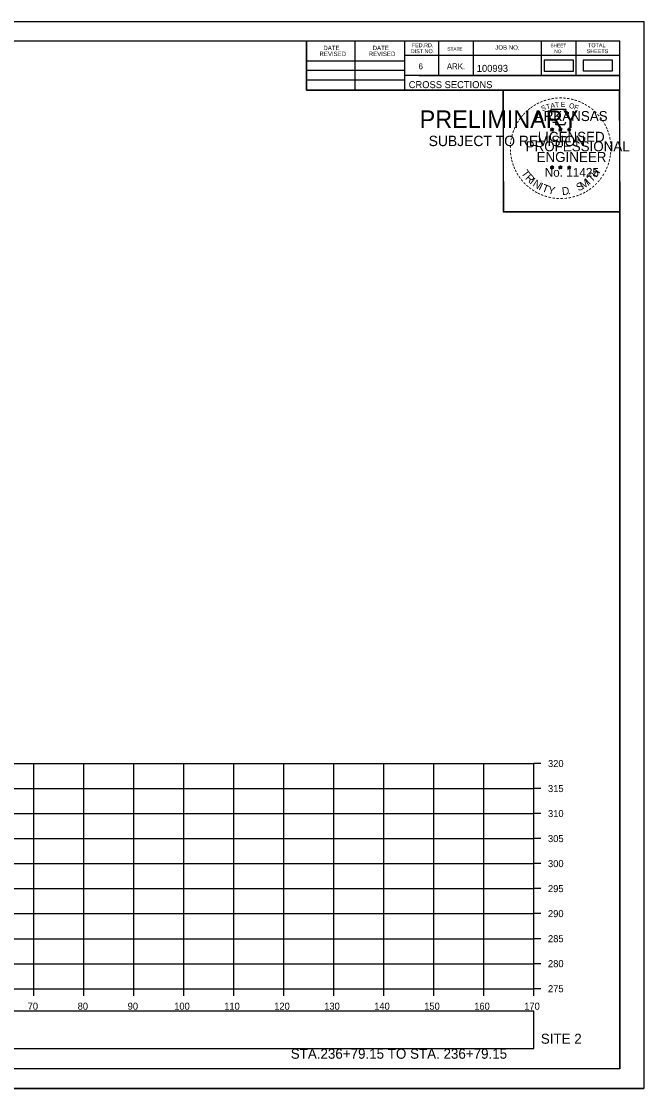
# Model space of a CAD drawing. Extents: x 4667 to 1632277, y -2100 to 724501.
# Drawn here: x 5844.7 to 5969.1, y 1663 to 1876.3 of the extents above; entities that cross this region are included whole.
import ezdxf

# ---------------------------------------------------------------- set-up
doc = ezdxf.new("R2010")
doc.units = 0
for name, color, linetype in [('Default', 7, 'Continuous'), ('R_Axis', 7, 'Continuous'), ('R_Axis Annot', 7, 'Continuous'), ('R_Border', 7, 'Continuous'), ('R_Border PE', 7, 'Continuous'), ('R_Border Prem', 7, 'Continuous'), ('R_Draft', 7, 'Continuous'), ('R_Grid', 7, 'Continuous'), ('R_No Plot', 7, 'Continuous'), ('R_Proposed CofA', 7, 'Continuous')]:
    doc.layers.add(name, color=color, linetype=linetype)

msp = doc.modelspace()

# ---------------------------------------------------------------- linework, layer by layer
at = {"layer": 'Default'}
for points in [[(5949.24, 1866.34), (5955.07, 1866.34), (5955.07, 1868.53), (5949.24, 1868.53)], [(5957.04, 1866.4), (5962.87, 1866.4), (5962.87, 1868.58), (5957.04, 1868.58)]]:
    msp.add_lwpolyline(points, close=True, dxfattribs=at)
at = {"layer": 'R_Axis'}
for p, q in [((5947.18, 1682.96), (5947.18, 1727.96)), ((5948.58, 1727.96), (5947.18, 1727.96)), ((5948.58, 1722.96), (5947.18, 1722.96)), ((5948.58, 1717.96), (5947.18, 1717.96)), ((5948.58, 1712.96), (5947.18, 1712.96)), ((5948.58, 1707.96), (5947.18, 1707.96)), ((5948.58, 1702.96), (5947.18, 1702.96)), ((5948.58, 1697.96), (5947.18, 1697.96)), ((5948.58, 1692.96), (5947.18, 1692.96)), ((5948.58, 1687.96), (5947.18, 1687.96)), ((5667.18, 1682.96), (5947.18, 1682.96)), ((5847.18, 1681.56), (5847.18, 1682.96)), ((5857.18, 1681.56), (5857.18, 1682.96)), ((5867.18, 1681.56), (5867.18, 1682.96)), ((5877.18, 1681.56), (5877.18, 1682.96)), ((5887.18, 1681.56), (5887.18, 1682.96)), ((5897.18, 1681.56), (5897.18, 1682.96)), ((5907.18, 1681.56), (5907.18, 1682.96)), ((5917.18, 1681.56), (5917.18, 1682.96)), ((5927.18, 1681.56), (5927.18, 1682.96)), ((5937.18, 1681.56), (5937.18, 1682.96)), ((5947.18, 1681.56), (5947.18, 1682.96)), ((5948.58, 1682.96), (5947.18, 1682.96))]:
    msp.add_line(p, q, dxfattribs=at)
at = {"layer": 'R_Border'}
for p, q in [((5648.18, 1872.42), (5964.36, 1872.42)), ((5901.72, 1862.54), (5901.72, 1872.42)), ((5911.4, 1862.54), (5911.4, 1872.42)), ((5921.26, 1872.42), (5921.26, 1862.54)), ((5928.1, 1872.42), (5928.1, 1865.48)), ((5935.04, 1872.42), (5935.04, 1865.48)), ((5948.62, 1872.42), (5948.62, 1865.48)), ((5955.56, 1872.42), (5955.56, 1865.48)), ((5964.36, 1666.96), (5964.36, 1872.42)), ((5964.36, 1869.48), (5921.26, 1869.48)), ((5964.36, 1869.5), (5964.36, 1869.5)), ((5901.72, 1868.4), (5921.26, 1868.4)), ((5901.72, 1866.54), (5921.26, 1866.54)), ((5901.72, 1864.6), (5921.26, 1864.6)), ((5964.36, 1865.48), (5921.26, 1865.48)), ((5924.22, 1865.48), (5964.36, 1865.48)), ((5964.36, 1862.54), (5901.72, 1862.54)), ((5964.36, 1666.96), (5648.18, 1666.96))]:
    msp.add_line(p, q, dxfattribs=at)
at = {"layer": 'R_Border PE'}
for p, q in [((5950.45, 1854.8), (5950.8, 1854.69)), ((5950.45, 1854.8), (5950.7, 1854.75)), ((5950.45, 1854.8), (5950.69, 1854.68)), ((5950.58, 1854.39), (5950.8, 1854.69)), ((5950.58, 1854.39), (5950.71, 1854.63)), ((5950.58, 1854.39), (5950.8, 1854.61)), ((5950.8, 1855.05), (5950.76, 1854.8)), ((5950.8, 1854.69), (5950.8, 1855.05)), ((5950.8, 1855.05), (5950.85, 1854.8)), ((5951.15, 1854.8), (5950.8, 1854.69)), ((5951.01, 1854.39), (5950.8, 1854.69)), ((5951.01, 1854.39), (5950.8, 1854.6)), ((5951.15, 1854.8), (5950.86, 1854.75)), ((5951.01, 1854.39), (5950.87, 1854.68)), ((5951.15, 1854.8), (5950.94, 1854.7)), ((5952.12, 1854.8), (5952.47, 1854.69)), ((5952.12, 1854.8), (5952.37, 1854.75)), ((5952.12, 1854.8), (5952.36, 1854.68)), ((5952.25, 1854.39), (5952.47, 1854.69)), ((5952.25, 1854.39), (5952.38, 1854.63)), ((5952.25, 1854.39), (5952.47, 1854.61)), ((5952.47, 1855.05), (5952.43, 1854.8)), ((5952.47, 1854.69), (5952.47, 1855.05)), ((5952.47, 1855.05), (5952.52, 1854.8)), ((5952.82, 1854.8), (5952.47, 1854.69)), ((5952.68, 1854.39), (5952.47, 1854.69)), ((5952.68, 1854.39), (5952.47, 1854.6)), ((5952.82, 1854.8), (5952.53, 1854.75)), ((5952.68, 1854.39), (5952.54, 1854.68)), ((5952.82, 1854.8), (5952.61, 1854.7)), ((5953.88, 1854.79), (5954.23, 1854.68)), ((5953.88, 1854.79), (5954.14, 1854.74)), ((5953.88, 1854.79), (5954.12, 1854.66)), ((5954.02, 1854.38), (5954.23, 1854.68)), ((5954.02, 1854.38), (5954.14, 1854.62)), ((5954.02, 1854.38), (5954.23, 1854.6)), ((5954.23, 1855.04), (5954.19, 1854.79)), ((5954.23, 1854.68), (5954.23, 1855.04)), ((5954.23, 1855.04), (5954.28, 1854.79)), ((5954.58, 1854.79), (5954.23, 1854.68)), ((5954.45, 1854.38), (5954.23, 1854.68)), ((5954.45, 1854.38), (5954.23, 1854.59)), ((5954.58, 1854.79), (5954.29, 1854.74)), ((5954.45, 1854.38), (5954.31, 1854.67)), ((5954.58, 1854.79), (5954.38, 1854.68)), ((5950.45, 1847.23), (5950.79, 1847.11)), ((5950.45, 1847.23), (5950.7, 1847.18)), ((5950.45, 1847.23), (5950.68, 1847.1)), ((5950.58, 1846.82), (5950.79, 1847.11)), ((5950.58, 1846.82), (5950.7, 1847.06)), ((5950.58, 1846.82), (5950.79, 1847.03)), ((5950.79, 1847.48), (5950.75, 1847.23)), ((5950.79, 1847.11), (5950.79, 1847.48)), ((5950.79, 1847.48), (5950.84, 1847.23)), ((5951.14, 1847.23), (5950.79, 1847.11)), ((5951.01, 1846.82), (5950.79, 1847.11)), ((5951.01, 1846.82), (5950.79, 1847.03)), ((5951.14, 1847.23), (5950.86, 1847.18)), ((5951.01, 1846.82), (5950.87, 1847.11)), ((5951.14, 1847.23), (5950.94, 1847.12)), ((5952.11, 1847.23), (5952.46, 1847.11)), ((5952.11, 1847.23), (5952.37, 1847.18)), ((5952.11, 1847.23), (5952.35, 1847.1)), ((5952.25, 1846.82), (5952.46, 1847.11)), ((5952.25, 1846.82), (5952.37, 1847.06)), ((5952.25, 1846.82), (5952.46, 1847.03)), ((5952.46, 1847.48), (5952.42, 1847.23)), ((5952.46, 1847.11), (5952.46, 1847.48)), ((5952.46, 1847.48), (5952.51, 1847.23)), ((5952.81, 1847.23), (5952.46, 1847.11)), ((5952.68, 1846.82), (5952.46, 1847.11)), ((5952.68, 1846.82), (5952.46, 1847.03)), ((5952.81, 1847.23), (5952.52, 1847.18)), ((5952.68, 1846.82), (5952.54, 1847.11)), ((5952.81, 1847.23), (5952.61, 1847.12)), ((5953.88, 1847.22), (5954.23, 1847.1)), ((5953.88, 1847.22), (5954.13, 1847.17)), ((5953.88, 1847.22), (5954.12, 1847.09)), ((5954.01, 1846.81), (5954.23, 1847.1)), ((5954.01, 1846.81), (5954.14, 1847.05)), ((5954.01, 1846.81), (5954.23, 1847.02)), ((5954.23, 1847.47), (5954.19, 1847.22)), ((5954.23, 1847.1), (5954.23, 1847.47)), ((5954.23, 1847.47), (5954.28, 1847.22)), ((5954.58, 1847.22), (5954.23, 1847.1)), ((5954.44, 1846.81), (5954.23, 1847.1)), ((5954.44, 1846.81), (5954.23, 1847.02)), ((5954.58, 1847.22), (5954.29, 1847.17)), ((5954.44, 1846.81), (5954.31, 1847.1)), ((5954.58, 1847.22), (5954.37, 1847.11))]:
    msp.add_line(p, q, dxfattribs=at)
for points in [[(5950.49, 1858.68), (5950.76, 1857.85)], [(5954, 1857.75), (5954.14, 1858.04), (5953.46, 1858.01), (5953.61, 1858.68), (5950.49, 1858.68)], [(5950.98, 1856.25), (5950.98, 1856.17), (5951.55, 1856.15), (5951.49, 1855.67), (5953.36, 1855.67), (5953.56, 1856.21)], [(5950.8, 1855.05), (5951.01, 1854.39), (5950.45, 1854.8), (5951.15, 1854.8), (5950.58, 1854.39), (5950.8, 1855.05)], [(5952.47, 1855.05), (5952.68, 1854.39), (5952.12, 1854.8), (5952.82, 1854.8), (5952.25, 1854.39), (5952.47, 1855.05)], [(5954.23, 1855.04), (5954.45, 1854.38), (5953.88, 1854.79), (5954.58, 1854.79), (5954.02, 1854.38), (5954.23, 1855.04)], [(5950.79, 1847.48), (5951.01, 1846.82), (5950.45, 1847.23), (5951.14, 1847.23), (5950.58, 1846.82), (5950.79, 1847.48)], [(5952.46, 1847.48), (5952.68, 1846.82), (5952.11, 1847.23), (5952.81, 1847.23), (5952.25, 1846.82), (5952.46, 1847.48)], [(5954.23, 1847.47), (5954.44, 1846.81), (5953.88, 1847.22), (5954.58, 1847.22), (5954.01, 1846.81), (5954.23, 1847.47)]]:
    msp.add_lwpolyline(points, dxfattribs=at)
for centre, radius in [((5950.8, 1854.69), 0.172), ((5950.8, 1854.69), 0.145), ((5950.8, 1854.69), 0.116), ((5950.8, 1854.69), 0.0991), ((5950.8, 1854.69), 0.0747), ((5950.8, 1854.69), 0.0495), ((5950.8, 1854.69), 0.0296), ((5952.47, 1854.69), 0.172), ((5952.47, 1854.69), 0.145), ((5952.47, 1854.69), 0.116), ((5952.47, 1854.69), 0.0991), ((5952.47, 1854.69), 0.0747), ((5952.47, 1854.69), 0.0495), ((5952.47, 1854.69), 0.0296), ((5954.23, 1854.67), 0.172), ((5954.23, 1854.67), 0.145), ((5954.23, 1854.67), 0.116), ((5954.23, 1854.67), 0.0991), ((5954.23, 1854.67), 0.0747), ((5954.23, 1854.67), 0.0495), ((5954.23, 1854.67), 0.0296), ((5950.79, 1847.11), 0.172), ((5950.79, 1847.11), 0.145), ((5950.79, 1847.11), 0.116), ((5950.79, 1847.11), 0.0991), ((5950.79, 1847.11), 0.0747), ((5950.79, 1847.11), 0.0495), ((5950.79, 1847.11), 0.0296), ((5952.46, 1847.11), 0.172), ((5952.46, 1847.11), 0.145), ((5952.46, 1847.11), 0.116), ((5952.46, 1847.11), 0.0991), ((5952.46, 1847.11), 0.0747), ((5952.46, 1847.11), 0.0495), ((5952.46, 1847.11), 0.0296), ((5954.23, 1847.1), 0.172), ((5954.23, 1847.1), 0.145), ((5954.23, 1847.1), 0.116), ((5954.23, 1847.1), 0.0991), ((5954.23, 1847.1), 0.0747), ((5954.23, 1847.1), 0.0495), ((5954.23, 1847.1), 0.0296)]:
    msp.add_circle(centre, radius, dxfattribs=at)
at = {"layer": 'R_Grid'}
for p, q in [((5667.18, 1727.96), (5947.18, 1727.96)), ((5847.18, 1682.96), (5847.18, 1727.96)), ((5857.18, 1682.96), (5857.18, 1727.96)), ((5867.18, 1682.96), (5867.18, 1727.96)), ((5877.18, 1682.96), (5877.18, 1727.96)), ((5887.18, 1682.96), (5887.18, 1727.96)), ((5897.18, 1682.96), (5897.18, 1727.96)), ((5907.18, 1682.96), (5907.18, 1727.96)), ((5917.18, 1682.96), (5917.18, 1727.96)), ((5927.18, 1682.96), (5927.18, 1727.96)), ((5937.18, 1682.96), (5937.18, 1727.96)), ((5947.18, 1682.96), (5947.18, 1727.96)), ((5667.18, 1722.96), (5947.18, 1722.96)), ((5667.18, 1717.96), (5947.18, 1717.96)), ((5667.18, 1712.96), (5947.18, 1712.96)), ((5667.18, 1707.96), (5947.18, 1707.96)), ((5667.18, 1702.96), (5947.18, 1702.96)), ((5667.18, 1697.96), (5947.18, 1697.96)), ((5667.18, 1692.96), (5947.18, 1692.96)), ((5667.18, 1687.96), (5947.18, 1687.96)), ((5667.18, 1682.96), (5947.18, 1682.96))]:
    msp.add_line(p, q, dxfattribs=at)
at = {"layer": 'R_No Plot'}
for p, q in [((5635.78, 1876.32), (5969.12, 1876.32)), ((5940.4, 1840.09), (5940.4, 1840.09)), ((5635.78, 1662.98), (5969.12, 1662.98))]:
    msp.add_line(p, q, dxfattribs=at)
for points in [[(5635.78, 1876.32), (5969.12, 1876.32), (5969.12, 1662.98), (5635.78, 1662.98)], [(5882.1, 1872.42), (5901.72, 1872.42), (5901.72, 1862.54), (5917.84, 1862.54), (5941.04, 1862.54), (5941.04, 1838.21), (5964.36, 1838.21), (5964.36, 1666.96), (5648.18, 1666.96), (5648.18, 1872.42)], [(5941.04, 1862.54), (5964.24, 1862.54), (5964.36, 1838.21), (5941.16, 1838.21)]]:
    msp.add_lwpolyline(points, close=True, dxfattribs=at)
at = {"layer": 'R_Proposed CofA'}
msp.add_lwpolyline([(5667.23, 1671.02), (5947.13, 1671.02), (5947.13, 1678.44), (5667.23, 1678.44)], close=True, dxfattribs=at)

# ---------------------------------------------------------------- texts
at = {"layer": 'R_Axis Annot'}
for s, p in [('320', (5949.98, 1727.26)), ('315', (5949.98, 1722.26)), ('310', (5949.98, 1717.26)), ('305', (5949.98, 1712.26)), ('300', (5949.98, 1707.26)), ('295', (5949.98, 1702.26)), ('290', (5949.98, 1697.26)), ('285', (5949.98, 1692.26)), ('280', (5949.98, 1687.26)), ('275', (5949.98, 1682.26)), ('70', (5845.92, 1678.76)), ('80', (5855.92, 1678.76)), ('90', (5865.92, 1678.76)), ('100', (5875.22, 1678.76)), ('110', (5885.22, 1678.76)), ('120', (5895.22, 1678.76)), ('130', (5905.22, 1678.76)), ('140', (5915.22, 1678.76)), ('150', (5925.22, 1678.76)), ('160', (5935.22, 1678.76)), ('170', (5945.22, 1678.76))]:
    msp.add_text(s, height=1.4, dxfattribs=at).set_placement(p)
at = {"layer": 'R_Border'}
for s, height, p in [('DATE', 0.879, (5905.06, 1870.56)), ('DATE', 0.879, (5914.92, 1870.56)), ('FED.RD.', 0.782, (5922.74, 1871.14)), ('STATE', 0.684, (5929.86, 1870.46)), ('JOB NO.', 0.879, (5939.44, 1870.66)), ('SHEET', 0.684, (5950.48, 1871.14)), ('TOTAL', 0.782, (5958, 1871.14)), ('REVISED', 0.879, (5904.28, 1869.38)), ('REVISED', 0.879, (5914.14, 1869.38)), ('DIST.NO.', 0.782, (5922.54, 1869.96)), ('NO.', 0.684, (5951.26, 1869.96)), ('SHEETS', 0.782, (5957.72, 1869.96)), ('6', 1.17, (5924.1, 1866.74)), ('ARK.', 1.172, (5929.76, 1866.74)), ('100993', 1.4, (5935.74, 1866.22)), ('CROSS SECTIONS', 1.4, (5922.13, 1862.97))]:
    msp.add_text(s, height=height, rotation=360, dxfattribs=at).set_placement(p)
at = {"layer": 'R_Border PE'}
for s, height, rotation, p in [('-', 1.6, 24.3072, (5948.6, 1859.53)), ('-', 1.6, 19.1761, (5949.24, 1859.8)), ('-', 1.6, 13.6301, (5949.99, 1860.04)), ('-', 1.6, 10.2193, (5950.67, 1860.21)), ('-', 1.6, 5.8968, (5951.39, 1860.32)), ('-', 1.6, 0.1862, (5952.17, 1860.39)), ('-', 1.6, 357.743, (5952.89, 1860.38)), ('-', 1.6, 352.1617, (5953.63, 1860.32)), ('-', 1.6, 347.2049, (5954.35, 1860.21)), ('-', 1.6, 342.3362, (5954.99, 1860.05)), ('-', 1.6, 337.8551, (5955.72, 1859.83)), ('-', 1.6, 42.9622, (5945.89, 1857.66)), ('-', 1.6, 38.9507, (5946.32, 1858.07)), ('-', 1.6, 36.2317, (5946.8, 1858.45)), ('-', 1.6, 34.0636, (5947.37, 1858.85)), ('ARKANSAS', 2, 360, (5947.34, 1856.39)), ('-', 1.6, 28.7918, (5947.97, 1859.22)), ('S', 1, 21.594, (5948.84, 1858.35)), ('T', 1, 16.4036, (5949.76, 1858.69)), ('A', 1, 11.2132, (5950.58, 1858.94)), ('T', 1, 6.0228, (5951.43, 1859.1)), ('E', 1, 0.8323, (5952.54, 1859.21)), ('O', 1, 350.4515, (5954.14, 1859)), ('F', 1, 340.0707, (5955.1, 1858.77)), ('-', 1.6, 334.1211, (5956.35, 1859.56)), ('-', 1.6, 329.6409, (5956.93, 1859.27)), ('-', 1.6, 325.8627, (5957.58, 1858.91)), ('-', 1.6, 320.5297, (5958.19, 1858.49)), ('-', 1.6, 315.5786, (5958.78, 1858)), ('-', 1.6, 58.0706, (5944.3, 1855.6)), ('-', 1.6, 54.2325, (5944.62, 1856.13)), ('-', 1.6, 50.6142, (5945.04, 1856.69)), ('-', 1.6, 48.423, (5945.44, 1857.18)), ('-', 1.6, 309.8797, (5959.35, 1857.45)), ('-', 1.6, 306.6522, (5959.88, 1856.85)), ('-', 1.4, 303.6753, (5960.36, 1856.28)), ('-', 1.6, 72.3945, (5943.51, 1853.74)), ('-', 1.6, 67.7743, (5943.73, 1854.37)), ('-', 1.6, 62.8713, (5943.98, 1854.99)), ('LICENSED', 2, 360, (5947.94, 1852.24)), ('DWB', 0.01, 360, (5950.79, 1854.68)), ('DWB', 0.01, 360, (5952.46, 1854.68)), ('DWB', 0.01, 360, (5954.22, 1854.67)), ('-', 1.6, 299.6684, (5960.68, 1855.67)), ('-', 1.6, 294.6628, (5961.01, 1855.06)), ('-', 1.6, 290.5728, (5961.26, 1854.48)), ('-', 1.6, 285.1233, (5961.5, 1853.9)), ('-', 1.6, 85.1863, (5943.1, 1851.63)), ('-', 1.6, 81.2013, (5943.18, 1852.32)), ('-', 1.6, 75.461, (5943.31, 1853.03)), ('PROFESSIONAL', 2, 360, (5945.52, 1850.34)), ('-', 1.6, 280.5493, (5961.7, 1853.16)), ('-', 1.6, 276.5962, (5961.86, 1852.39)), ('-', 1.6, 94.1959, (5943.11, 1850.2)), ('-', 1.6, 89.0622, (5943.08, 1850.93)), ('-', 1.6, 98.9479, (5943.18, 1849.53)), ('ENGINEER', 2, 360, (5947.7, 1848.21)), ('-', 1.6, 263.5172, (5961.94, 1850.37)), ('-', 1.6, 274.3301, (5961.92, 1851.67)), ('-', 1.6, 269.9407, (5961.95, 1851.04)), ('-', 1.6, 101.7149, (5943.32, 1848.8)), ('-', 1.6, 105.4578, (5943.48, 1848.21)), ('-', 1.6, 109.0874, (5943.7, 1847.57)), ('-', 1.6, 252.8681, (5961.57, 1848.32)), ('-', 1.6, 255.7626, (5961.75, 1849.04)), ('-', 1.6, 260.9953, (5961.86, 1849.72)), ('-', 1.6, 114.0643, (5943.95, 1846.98)), ('-', 1.6, 115.7289, (5944.25, 1846.36)), ('-', 1.6, 120.4471, (5944.61, 1845.77)), ('-', 1.6, 125.8934, (5945.01, 1845.21)), ('T', 1.54, 306.0406, (5944.55, 1845.95)), ('R', 1.54, 314.005, (5945.32, 1844.91)), ('No. 11425', 1.757, 360, (5949.33, 1845.26)), ('DWB', 0.01, 360, (5950.78, 1847.11)), ('DWB', 0.01, 360, (5952.45, 1847.11)), ('DWB', 0.01, 360, (5954.22, 1847.1)), ('T', 1.54, 46.6444, (5958.78, 1844.05)), ('H', 1.54, 54.6088, (5959.67, 1844.99)), ('-', 1.6, 239.0712, (5960.69, 1846.27)), ('-', 1.6, 244.6197, (5961.09, 1847.02)), ('-', 1.6, 247.8887, (5961.35, 1847.65)), ('-', 1.6, 130.7181, (5945.48, 1844.66)), ('-', 1.6, 134.2238, (5945.99, 1844.12)), ('-', 1.6, 138.9338, (5946.52, 1843.65)), ('I', 1.54, 321.9694, (5946.22, 1843.97)), ('N', 1.54, 326.5002, (5946.78, 1843.5)), ('I', 1.54, 335.3603, (5947.99, 1842.72)), ('T', 1.54, 339.8912, (5948.65, 1842.39)), ('Y', 1.54, 347.8556, (5949.87, 1841.94)), ('S', 1.54, 26.9312, (5956.1, 1842.31)), ('M', 1.54, 32.6563, (5956.94, 1842.72)), ('I', 1.54, 42.1136, (5958.22, 1843.57)), ('-', 1.6, 221.0851, (5958.86, 1843.97)), ('-', 1.6, 225.7653, (5959.38, 1844.48)), ('-', 1.6, 231.2538, (5959.86, 1845.05)), ('-', 1.6, 233.8452, (5960.29, 1845.61)), ('-', 1.6, 144.6463, (5947.07, 1843.25)), ('-', 1.6, 148.0898, (5947.64, 1842.88)), ('-', 1.6, 151.5704, (5948.21, 1842.55)), ('-', 1.6, 154.6002, (5948.74, 1842.3)), ('-', 1.6, 158.5612, (5949.36, 1842.05)), ('-', 1.6, 162.7983, (5950.05, 1841.84)), ('-', 1.6, 167.5555, (5950.76, 1841.67)), ('-', 1.6, 173.1155, (5951.53, 1841.56)), ('D', 1.54, 6.3969, (5952.85, 1841.58)), ('-', 1.6, 191.2858, (5954.57, 1841.74)), ('.', 1.54, 13.7642, (5954.05, 1841.71)), ('-', 1.6, 195.4743, (5955.3, 1841.94)), ('-', 1.6, 200.7184, (5955.98, 1842.18)), ('-', 1.6, 204.2516, (5956.6, 1842.45)), ('-', 1.6, 207.3568, (5957.22, 1842.77)), ('-', 1.6, 212.2491, (5957.78, 1843.12)), ('-', 1.6, 215.7363, (5958.31, 1843.5)), ('-', 1.6, 176.5183, (5952.28, 1841.51)), ('-', 1.6, 181.5918, (5953.03, 1841.53)), ('-', 1.6, 185.8167, (5953.84, 1841.6))]:
    msp.add_text(s, height=height, rotation=rotation, dxfattribs=at).set_placement(p)
at = {"layer": 'R_Border Prem'}
for s, height, p in [('PRELIMINARY', 3.5, (5924.32, 1855.01)), ('DWB', 0.01, (5925.06, 1856.86)), ('SUBJECT TO REVISION', 2.0751, (5926.12, 1851.38))]:
    msp.add_text(s, height=height, rotation=360, dxfattribs=at).set_placement(p)
at = {"layer": 'R_Draft'}
for s, p in [('SITE 2', (5948.55, 1671.96)), ('STA.236+79.15 TO STA. 236+79.15', (5898.54, 1668.96))]:
    msp.add_text(s, height=2, dxfattribs=at).set_placement(p)

doc.saveas('drawing.dxf')
